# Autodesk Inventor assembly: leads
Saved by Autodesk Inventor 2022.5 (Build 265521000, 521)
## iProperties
Created: 2024-12
Part Number: leads
Document SubType Name: Assembly
Designer: AdminForWorker
Title: leads
Author: AdminForWorker
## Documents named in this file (6)
- c:\worker\convert-fusion-r05-cosv3\tmp\job-1\35\temp\files\545dca92-a972-481a-9197-dd1a1176500e\leads.iam
- c:\worker\convert-fusion-r05-cosv3\tmp\job-1\35\temp\files\545dca92-a972-481a-9197-dd1a1176500e\Component12.ipt
- c:\worker\convert-fusion-r05-cosv3\tmp\job-1\35\temp\files\545dca92-a972-481a-9197-dd1a1176500e\Component13.ipt
- c:\worker\convert-fusion-r05-cosv3\tmp\job-1\35\temp\files\545dca92-a972-481a-9197-dd1a1176500e\Component14.ipt
- c:\worker\convert-fusion-r05-cosv3\tmp\job-1\35\temp\files\545dca92-a972-481a-9197-dd1a1176500e\Component15.ipt
- c:\worker\convert-fusion-r05-cosv3\tmp\job-1\35\temp\files\545dca92-a972-481a-9197-dd1a1176500e\Component16.ipt
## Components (10 placed, 5 different names)
1. Component12:1
2. Component13:1
3. Component12:2
4. Component12:3
5. Component12:4
6. Component12:5
7. Component14:1
8. Component14:2
9. Component15:1
10. Component16:1
